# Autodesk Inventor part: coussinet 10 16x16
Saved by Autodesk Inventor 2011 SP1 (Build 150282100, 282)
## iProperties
Created: 2010-12
Part Number: coussinet 10 16x16
Document SubType Name: Modeling
Designer: eric
Density: 1 g/cm^3
Author: eric
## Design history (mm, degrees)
feature "Base1"
node "Solide1"
node "Corps solides"
node "Corps surfaciques"
